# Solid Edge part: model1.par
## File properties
Author: Vicky Raina
Template: normal.par
Last saved by: Robert a Rhodes jr
Revision: 5
Application: Solid Edge
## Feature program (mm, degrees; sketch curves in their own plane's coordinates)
sketch for "unnamed Protrusion 1" plane through (0, 0, 0) normal (0, -1, 0) x-axis (1, 0, 0)
  arc centre (60, 0) radius 30 from (60, 30) to (60, -30) cw
  line (104, -30) -> (60, -30)
  line (104, 18) -> (104, -30)
  line (164, 18) -> (104, 18)
  line (164, -4) -> (164, 18)
  line (182, -4) -> (164, -4)
  line (182, -4) -> (182, 36)
  line (142, 36) -> (182, 36)
  line (142, 30) -> (142, 36)
  line (60, 30) -> (142, 30)
extrude "unnamed Protrusion 1" add finite 54 symmetric
sketch for "unnamed Protrusion 2" #1 plane through (0, 0, 0) normal (0, -1, 0) x-axis (1, 0, 0)
  arc centre (60, 0) radius 30 from (60, 30) to (60, -30) ccw
  arc centre (60, 0) radius 30 from (60, 30) to (60, -30) cw
sketch for "unnamed Protrusion 2" #2 plane through (0, 0, 0) normal (0, -1, 0) x-axis (1, 0, 0)
  circle centre (60, 0) radius 18
extrude "unnamed Protrusion 2" add finite 66 symmetric
sketch for "unnamed Protrusion 3" plane through (0, 0, 0) normal (0, -1, 0) x-axis (1, 0, 0)
  line (104, -30) -> (164, -4)
  line (164, -4) -> (164, 18)
  line (164, 18) -> (104, 18)
  line (104, 18) -> (104, -30)
extrude "unnamed Protrusion 3" add finite 18 symmetric
sketch for "unnamed Protrusion 4" plane through (0, 0, 0) normal (0, -1, 0) x-axis (1, 0, 0)
  line (200, 76) -> (200, -4)
  line (200, -4) -> (182, -4)
  line (182, -4) -> (182, 36)
  line (182, 76) -> (182, 36)
  line (182, 76) -> (200, 76)
extrude "unnamed Protrusion 4" add finite 92 symmetric
sketch for "unnamed Protrusion 5" plane through (0, 0, 0) normal (0, -1, 0) x-axis (1, 0, 0)
  line (142, 36) -> (182, 76)
  line (182, 76) -> (182, 36)
  line (142, 36) -> (182, 36)
extrude "unnamed Protrusion 5" add finite 12 symmetric
sketch for "unnamed Hole 1" plane through (200, 0, 36) normal (1, 0, 0) x-axis (0, 1, 0)
hole "unnamed Hole 1" through
sketch for "unnamed Hole 2" plane through (200, 0, 36) normal (1, 0, 0) x-axis (0, 1, 0)
  hole centre (-30, 22) bore radius 8
hole "unnamed Hole 2" through
pattern "unnamed Pattern 1" of "unnamed Hole 1", "unnamed Hole 2"
fillet "unnamed Round 1"
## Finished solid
Body 1: solid body, 34 faces, 81 edges, 46 vertices.
  Faces by surface: plane 28, cylinder 6
  Edges by curve: line 67, circle 14
Bounding box of the edges (mm): 170.000 x 92.000 x 106.000, from (30, -46, -30) to (200, 46, 76).
Cylindrical faces by radius (mm): R8 x2, R16 x2, R18 x1, R30 x1
Planar faces by outward normal: +x 3, +y 5, +z 4, -x 5, -y 5, -z 4, oblique 2
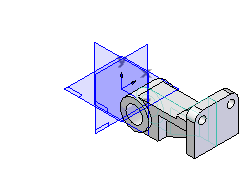
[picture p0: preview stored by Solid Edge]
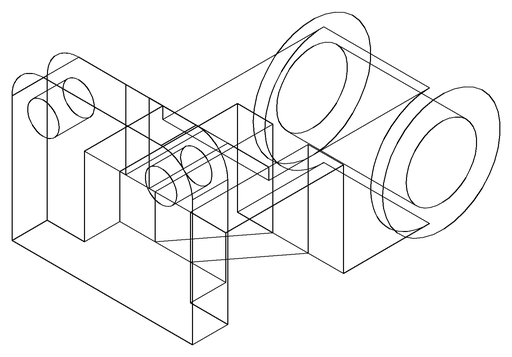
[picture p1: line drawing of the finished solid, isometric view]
